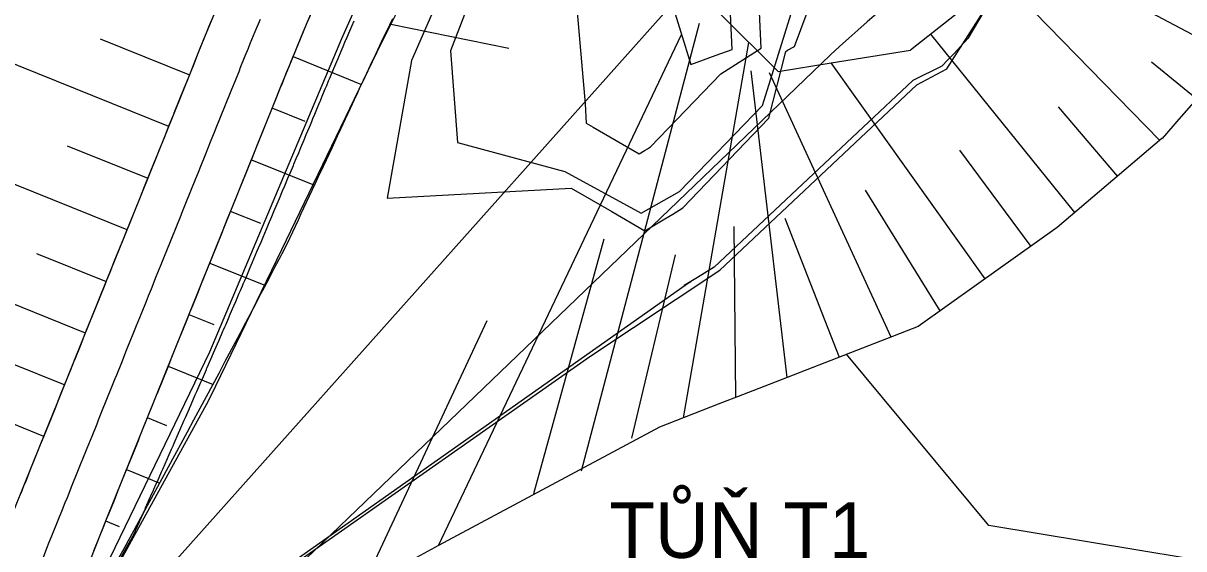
# Model space of a CAD drawing. Extents: x -564037 to -563722, y -1163561 to -1163412.
# Drawn here: x -563977.45 to -563951.42, y -1163497.4 to -1163485.61 of the extents above; entities that cross this region are included whole.
import ezdxf

# ---------------------------------------------------------------- set-up
doc = ezdxf.new("R2010")
doc.units = 0
for name, color, linetype in [('4', 7, 'Continuous'), ('5', 7, 'Continuous'), ('Default', 7, 'Continuous'), ('Line', 7, 'Continuous')]:
    doc.layers.add(name, color=color, linetype=linetype)

msp = doc.modelspace()

# ---------------------------------------------------------------- linework, layer by layer
for points in [[(-563976.663, -1163501.462), (-563964.742, -1163493.091), (-563961.829, -1163491.15), (-563957.41, -1163486.988), (-563956.735, -1163486.627), (-563953.281, -1163481.221), (-563953.993, -1163478.343), (-563957.796, -1163470.824), (-563957.81, -1163470.439), (-563957.835, -1163469.754), (-563958.239, -1163469.063), (-563958.187, -1163468.683), (-563959.529, -1163466.077), (-563960.166, -1163464.984), (-563964.31, -1163473.527), (-563966.903, -1163478.544), (-563968.406, -1163481.669), (-563970.316, -1163485.955), (-563973.278, -1163492.988), (-563976.735, -1163500.155), (-563977.161, -1163500.889), (-563977.363, -1163501.307)], [(-563962.125, -1163475.875), (-563962.765, -1163475.108), (-563963.856, -1163475.351), (-563965.212, -1163477.785), (-563966.919, -1163483.486), (-563967.557, -1163485.407), (-563967.871, -1163486.226), (-563967.716, -1163488.285), (-563965.306, -1163488.933), (-563963.594, -1163489.868), (-563962.736, -1163489.387), (-563960.869, -1163487.453), (-563959.333, -1163482.497), (-563959.613, -1163479.666)], [(-563962.48, -1163486.536), (-563961.911, -1163486.326), (-563961.553, -1163486.194), (-563961.747, -1163482.024), (-563961.878, -1163479.201), (-563962.246, -1163479.103), (-563962.794, -1163479.244), (-563962.818, -1163479.245), (-563963.128, -1163481.546), (-563962.901, -1163485.181)]]:
    msp.add_lwpolyline(points, close=True)
for points in [[(-563975.396, -1163497.906), (-563973.296, -1163494.084), (-563973.133, -1163493.747), (-563971.654, -1163490.682), (-563969.513, -1163486.248), (-563968.702, -1163484.611), (-563968.142, -1163483.478), (-563966.349, -1163479.855), (-563965.958, -1163479.067), (-563964.584, -1163476.289), (-563963.373, -1163473.843), (-563963.192, -1163473.475), (-563963.191, -1163473.474), (-563962.456, -1163471.989), (-563961.948, -1163470.647), (-563961.634, -1163469.818)], [(-563960.523, -1163486.688), (-563961.829, -1163485.385), (-563962.324, -1163483.708), (-563962.461, -1163482.584), (-563962.597, -1163481.459), (-563962.579, -1163480.501), (-563961.736, -1163479.195), (-563961.088, -1163479.165), (-563960.669, -1163479.145), (-563960.089, -1163479.118), (-563959.09, -1163479.072), (-563958.091, -1163479.026), (-563957.266, -1163478.987), (-563957.092, -1163478.979), (-563955.995, -1163480.274), (-563955.699, -1163482.25), (-563955.954, -1163483.392), (-563956.177, -1163485.128), (-563956.177, -1163485.128), (-563956.177, -1163485.128), (-563957.55, -1163486.21)], [(-563965.051, -1163485.101), (-563964.85, -1163487.418), (-563964.83, -1163487.847), (-563964.668, -1163487.941), (-563963.636, -1163488.535), (-563963.502, -1163488.454), (-563963.449, -1163488.423), (-563963.381, -1163488.382), (-563961.809, -1163486.742), (-563960.902, -1163486.164), (-563961.157, -1163480.663)], [(-563968.084, -1163484.934), (-563968.744, -1163486.445), (-563969.289, -1163489.534), (-563965.164, -1163489.309), (-563965.164, -1163489.309), (-563964.25, -1163489.835), (-563963.508, -1163490.263), (-563963.061, -1163489.994), (-563962.883, -1163489.889), (-563962.657, -1163489.751), (-563960.727, -1163487.738), (-563960.348, -1163486.241), (-563960.31, -1163486.212), (-563960.154, -1163486.129), (-563958.95, -1163482.892)], [(-563977.812, -1163496.922), (-563977.438, -1163495.994), (-563977.065, -1163495.066), (-563976.691, -1163494.139), (-563976.318, -1163493.211), (-563975.945, -1163492.283), (-563975.571, -1163491.355), (-563975.198, -1163490.428), (-563974.825, -1163489.5), (-563974.451, -1163488.572), (-563974.078, -1163487.645), (-563973.705, -1163486.717), (-563973.527, -1163486.276), (-563973.328, -1163485.785), (-563972.941, -1163484.852)], [(-563975.956, -1163497.668), (-563975.583, -1163496.741), (-563975.209, -1163495.813), (-563974.836, -1163494.885), (-563974.463, -1163493.958), (-563974.089, -1163493.03), (-563973.716, -1163492.102), (-563973.343, -1163491.175), (-563972.969, -1163490.247), (-563972.596, -1163489.319), (-563972.223, -1163488.391), (-563971.849, -1163487.464), (-563971.672, -1163487.023), (-563971.476, -1163486.542), (-563971.097, -1163485.627), (-563970.817, -1163484.966)], [(-563977.502, -1163496.152), (-563977.438, -1163495.994), (-563977.391, -1163495.877), (-563977.28, -1163495.601), (-563977.169, -1163495.326), (-563977.065, -1163495.066), (-563977.059, -1163495.051), (-563976.948, -1163494.775), (-563976.837, -1163494.5), (-563976.726, -1163494.225), (-563976.691, -1163494.139), (-563976.615, -1163493.949), (-563976.505, -1163493.674), (-563976.394, -1163493.399), (-563976.318, -1163493.211), (-563976.283, -1163493.123), (-563976.172, -1163492.848), (-563976.061, -1163492.573), (-563975.95, -1163492.297), (-563975.945, -1163492.283), (-563975.84, -1163492.022), (-563975.729, -1163491.747), (-563975.618, -1163491.471), (-563975.571, -1163491.355), (-563975.507, -1163491.196), (-563975.396, -1163490.921), (-563975.286, -1163490.645), (-563975.198, -1163490.428), (-563975.175, -1163490.37), (-563975.064, -1163490.095), (-563974.953, -1163489.819), (-563974.842, -1163489.544), (-563974.825, -1163489.5), (-563974.732, -1163489.269), (-563974.621, -1163488.994), (-563974.51, -1163488.718), (-563974.451, -1163488.572), (-563974.399, -1163488.443), (-563974.288, -1163488.168), (-563974.177, -1163487.892), (-563974.078, -1163487.645), (-563974.067, -1163487.617), (-563973.956, -1163487.342), (-563973.845, -1163487.066), (-563973.734, -1163486.791), (-563973.705, -1163486.717), (-563973.623, -1163486.516), (-563973.527, -1163486.276), (-563973.512, -1163486.24), (-563973.4, -1163485.962), (-563973.328, -1163485.785), (-563973.287, -1163485.685), (-563973.173, -1163485.407)], [(-563977.017, -1163497.627), (-563976.907, -1163497.351), (-563976.884, -1163497.295), (-563976.796, -1163497.076), (-563976.685, -1163496.801), (-563976.574, -1163496.525), (-563976.511, -1163496.367), (-563976.463, -1163496.25), (-563976.353, -1163495.975), (-563976.242, -1163495.699), (-563976.137, -1163495.44), (-563976.131, -1163495.424), (-563976.02, -1163495.149), (-563975.909, -1163494.873), (-563975.798, -1163494.598), (-563975.764, -1163494.512), (-563975.688, -1163494.323), (-563975.577, -1163494.047), (-563975.466, -1163493.772), (-563975.39, -1163493.584), (-563975.355, -1163493.497), (-563975.244, -1163493.221), (-563975.134, -1163492.946), (-563975.023, -1163492.671), (-563975.017, -1163492.657), (-563974.912, -1163492.395), (-563974.801, -1163492.12), (-563974.69, -1163491.845), (-563974.644, -1163491.729), (-563974.58, -1163491.569), (-563974.469, -1163491.294), (-563974.358, -1163491.019), (-563974.27, -1163490.801), (-563974.247, -1163490.744), (-563974.136, -1163490.468), (-563974.025, -1163490.193), (-563973.915, -1163489.918), (-563973.897, -1163489.873), (-563973.804, -1163489.642), (-563973.693, -1163489.367), (-563973.582, -1163489.092), (-563973.524, -1163488.946), (-563973.471, -1163488.816), (-563973.361, -1163488.541), (-563973.25, -1163488.266), (-563973.15, -1163488.018), (-563973.139, -1163487.99), (-563973.028, -1163487.715), (-563972.917, -1163487.44), (-563972.807, -1163487.164), (-563972.777, -1163487.09), (-563972.696, -1163486.889), (-563972.599, -1163486.649), (-563972.585, -1163486.614), (-563972.474, -1163486.339), (-563972.402, -1163486.163), (-563972.361, -1163486.064), (-563972.249, -1163485.789), (-563972.135, -1163485.515)], [(-563975.868, -1163497.449), (-563975.757, -1163497.174), (-563975.646, -1163496.899), (-563975.583, -1163496.741), (-563975.536, -1163496.623), (-563975.425, -1163496.348), (-563975.314, -1163496.073), (-563975.209, -1163495.813), (-563975.203, -1163495.797), (-563975.092, -1163495.522), (-563974.982, -1163495.247), (-563974.871, -1163494.971), (-563974.836, -1163494.885), (-563974.76, -1163494.696), (-563974.649, -1163494.421), (-563974.538, -1163494.145), (-563974.463, -1163493.958), (-563974.428, -1163493.87), (-563974.317, -1163493.595), (-563974.206, -1163493.319), (-563974.095, -1163493.044), (-563974.089, -1163493.03), (-563973.984, -1163492.769), (-563973.873, -1163492.493), (-563973.763, -1163492.218), (-563973.716, -1163492.102), (-563973.652, -1163491.943), (-563973.541, -1163491.668), (-563973.43, -1163491.392), (-563973.343, -1163491.175), (-563973.319, -1163491.117), (-563973.209, -1163490.842), (-563973.098, -1163490.566), (-563972.987, -1163490.291), (-563972.969, -1163490.247), (-563972.876, -1163490.016), (-563972.765, -1163489.74), (-563972.655, -1163489.465), (-563972.596, -1163489.319), (-563972.544, -1163489.19), (-563972.433, -1163488.914), (-563972.322, -1163488.639), (-563972.223, -1163488.391), (-563972.211, -1163488.364), (-563972.101, -1163488.088), (-563971.99, -1163487.813), (-563971.879, -1163487.538), (-563971.849, -1163487.464), (-563971.768, -1163487.262), (-563971.672, -1163487.023), (-563971.657, -1163486.987), (-563971.547, -1163486.715), (-563971.476, -1163486.542), (-563971.436, -1163486.443), (-563971.324, -1163486.171), (-563971.212, -1163485.9), (-563971.098, -1163485.629), (-563971.097, -1163485.627), (-563970.984, -1163485.358)], [(-563975.336, -1163497.663), (-563975.193, -1163497.401), (-563975.049, -1163497.139), (-563974.967, -1163496.989), (-563974.906, -1163496.877), (-563974.763, -1163496.614), (-563974.62, -1163496.352), (-563974.485, -1163496.104), (-563974.477, -1163496.09), (-563974.335, -1163495.827), (-563974.192, -1163495.564), (-563974.05, -1163495.302), (-563974.006, -1163495.219), (-563973.909, -1163495.039), (-563973.767, -1163494.776), (-563973.625, -1163494.513), (-563973.529, -1163494.333), (-563973.484, -1163494.25), (-563973.343, -1163493.987), (-563973.202, -1163493.723), (-563973.062, -1163493.46), (-563973.055, -1163493.446), (-563972.922, -1163493.196), (-563972.782, -1163492.933), (-563972.642, -1163492.669), (-563972.583, -1163492.558), (-563972.502, -1163492.405), (-563972.363, -1163492.142), (-563972.224, -1163491.878), (-563972.114, -1163491.669), (-563972.085, -1163491.614), (-563971.946, -1163491.35), (-563971.808, -1163491.085), (-563971.669, -1163490.821), (-563971.647, -1163490.779), (-563971.537, -1163490.555), (-563971.41, -1163490.286), (-563971.283, -1163490.017), (-563971.216, -1163489.874), (-563971.157, -1163489.748), (-563971.03, -1163489.479), (-563970.904, -1163489.21), (-563970.791, -1163488.968), (-563970.778, -1163488.94), (-563970.653, -1163488.671), (-563970.527, -1163488.402), (-563970.402, -1163488.132), (-563970.368, -1163488.06), (-563970.277, -1163487.863), (-563970.168, -1163487.628), (-563970.152, -1163487.594), (-563970.03, -1163487.332), (-563969.952, -1163487.164), (-563969.908, -1163487.069), (-563969.785, -1163486.808), (-563969.662, -1163486.546), (-563969.538, -1163486.285), (-563969.537, -1163486.283), (-563969.414, -1163486.024), (-563969.289, -1163485.763), (-563969.233, -1163485.646), (-563969.164, -1163485.502)], [(-563975.336, -1163497.663), (-563975.193, -1163497.401), (-563975.049, -1163497.139), (-563974.967, -1163496.989), (-563974.906, -1163496.877), (-563974.763, -1163496.614), (-563974.62, -1163496.352), (-563974.485, -1163496.104), (-563974.477, -1163496.09), (-563974.335, -1163495.827), (-563974.192, -1163495.564), (-563974.05, -1163495.302), (-563974.006, -1163495.219), (-563973.909, -1163495.039), (-563973.767, -1163494.776), (-563973.625, -1163494.513), (-563973.529, -1163494.333), (-563973.484, -1163494.25), (-563973.343, -1163493.987), (-563973.202, -1163493.723), (-563973.062, -1163493.46), (-563973.055, -1163493.446), (-563972.922, -1163493.196), (-563972.782, -1163492.933), (-563972.642, -1163492.669), (-563972.583, -1163492.558), (-563972.502, -1163492.405), (-563972.363, -1163492.142), (-563972.224, -1163491.878), (-563972.114, -1163491.669), (-563972.085, -1163491.614), (-563971.946, -1163491.35), (-563971.808, -1163491.085), (-563971.669, -1163490.821), (-563971.647, -1163490.779), (-563971.537, -1163490.555), (-563971.41, -1163490.286), (-563971.283, -1163490.017), (-563971.216, -1163489.874), (-563971.157, -1163489.748), (-563971.03, -1163489.479), (-563970.904, -1163489.21), (-563970.791, -1163488.968), (-563970.778, -1163488.94), (-563970.653, -1163488.671), (-563970.527, -1163488.402), (-563970.402, -1163488.132), (-563970.368, -1163488.06), (-563970.277, -1163487.863), (-563970.168, -1163487.628), (-563970.152, -1163487.594), (-563970.03, -1163487.332), (-563969.952, -1163487.164), (-563969.908, -1163487.069), (-563969.785, -1163486.808), (-563969.662, -1163486.546), (-563969.538, -1163486.285), (-563969.537, -1163486.283), (-563969.414, -1163486.024), (-563969.289, -1163485.763), (-563969.233, -1163485.646), (-563969.164, -1163485.502)], [(-563960.523, -1163486.688), (-563959.331, -1163486.495), (-563957.55, -1163486.21)], [(-563950.476, -1163486.561), (-563951.53, -1163487.762), (-563951.667, -1163487.917), (-563951.91, -1163488.194), (-563951.913, -1163488.197), (-563954.263, -1163490.192), (-563956.079, -1163491.487), (-563957.379, -1163492.414), (-563960.591, -1163493.664), (-563961.319, -1163493.948), (-563961.866, -1163494.161), (-563963.182, -1163494.674), (-563968.138, -1163497.33), (-563968.634, -1163497.596)], [(-563940.257, -1163499.457), (-563955.795, -1163496.878), (-563958.985, -1163493.039)]]:
    msp.add_lwpolyline(points)
at = {"layer": '5'}
msp.add_line((-563974.94, -1163501.303), (-563959.546, -1163486.507), dxfattribs=at)
msp.add_arc((-563942.222, -1163504.531), 25, 113.6313, 133.8653, dxfattribs=at)
at = {"layer": 'Default'}
for points in [[(-563957.93, -1163469.965), (-563958.016, -1163470.367), (-563958.027, -1163470.695), (-563958.032, -1163470.72), (-563958.032, -1163470.72), (-563954.123, -1163478.457), (-563954.123, -1163478.457), (-563954.123, -1163478.457), (-563954.115, -1163478.547), (-563954.115, -1163478.547), (-563953.444, -1163481.184), (-563956.263, -1163485.948), (-563956.577, -1163486.293), (-563956.711, -1163486.426), (-563956.848, -1163486.572), (-563957.497, -1163486.891), (-563961.953, -1163491.085), (-563962.333, -1163491.316), (-563962.631, -1163491.492), (-563962.482, -1163491.404), (-563976.56, -1163501.343)], [(-563977.332, -1163501.295), (-563974.976, -1163497.082), (-563974.974, -1163497.079), (-563974.939, -1163497), (-563974.935, -1163496.992), (-563974.849, -1163496.797), (-563974.841, -1163496.78), (-563974.722, -1163496.513), (-563974.711, -1163496.488), (-563974.596, -1163496.229), (-563974.589, -1163496.212), (-563974.532, -1163496.085), (-563974.525, -1163496.068), (-563974.47, -1163495.944), (-563974.453, -1163495.906), (-563974.344, -1163495.659), (-563974.324, -1163495.615), (-563974.218, -1163495.374), (-563974.203, -1163495.339), (-563974.128, -1163495.17), (-563974.122, -1163495.155), (-563974.093, -1163495.09), (-563974.069, -1163495.034), (-563973.968, -1163494.805), (-563973.941, -1163494.744), (-563973.843, -1163494.52), (-563973.816, -1163494.459), (-563973.727, -1163494.254), (-563973.725, -1163494.249), (-563973.718, -1163494.234), (-563973.688, -1163494.165), (-563973.594, -1163493.949), (-563973.562, -1163493.876), (-563973.47, -1163493.664), (-563973.436, -1163493.586), (-563973.346, -1163493.378), (-563973.341, -1163493.366), (-563973.328, -1163493.337), (-563973.297, -1163493.267), (-563973.222, -1163493.093), (-563973.185, -1163493.008), (-563973.099, -1163492.807), (-563973.061, -1163492.719), (-563972.975, -1163492.522), (-563972.961, -1163492.488), (-563972.931, -1163492.418), (-563972.905, -1163492.359), (-563972.852, -1163492.236), (-563972.812, -1163492.141), (-563972.729, -1163491.95), (-563972.688, -1163491.852), (-563972.607, -1163491.664), (-563972.582, -1163491.606), (-563972.536, -1163491.499), (-563972.518, -1163491.456), (-563972.485, -1163491.378), (-563972.441, -1163491.275), (-563972.363, -1163491.092), (-563972.318, -1163490.986), (-563972.241, -1163490.805), (-563972.204, -1163490.719), (-563972.145, -1163490.579), (-563972.135, -1163490.556), (-563972.119, -1163490.519), (-563972.072, -1163490.408), (-563971.998, -1163490.232), (-563971.95, -1163490.12), (-563971.877, -1163489.946), (-563971.829, -1163489.833), (-563971.756, -1163489.659), (-563971.756, -1163489.659), (-563971.755, -1163489.658), (-563971.707, -1163489.544), (-563971.635, -1163489.372), (-563971.587, -1163489.257), (-563971.515, -1163489.086), (-563971.466, -1163488.969), (-563971.395, -1163488.799), (-563971.384, -1163488.773), (-563971.368, -1163488.735), (-563971.33, -1163488.644), (-563971.275, -1163488.512), (-563971.225, -1163488.393), (-563971.155, -1163488.224), (-563971.105, -1163488.105), (-563971.036, -1163487.937), (-563971.014, -1163487.885), (-563970.984, -1163487.812), (-563970.955, -1163487.744), (-563970.916, -1163487.65), (-563970.868, -1163487.533), (-563970.802, -1163487.373), (-563970.8, -1163487.368), (-563970.797, -1163487.363), (-563970.747, -1163487.242), (-563970.68, -1163487.081), (-563970.647, -1163487.002), (-563970.604, -1163486.898), (-563970.586, -1163486.855), (-563970.563, -1163486.799), (-563970.511, -1163486.677), (-563970.445, -1163486.518), (-563970.392, -1163486.395), (-563970.326, -1163486.237), (-563970.28, -1163486.13), (-563970.222, -1163485.995), (-563970.215, -1163485.978), (-563970.206, -1163485.957), (-563970.153, -1163485.832), (-563970.086, -1163485.676), (-563970.032, -1163485.551)]]:
    msp.add_lwpolyline(points, dxfattribs=at)
at = {"layer": 'Line'}
for p, q in [((-563950.389, -1163486.314), (-563955.948, -1163483.346)), ((-563951.96, -1163488.236), (-563956.04, -1163484.057)), ((-563962.901, -1163485.181), (-563977.279, -1163501.298)), ((-563966.564, -1163486.174), (-563969.208, -1163485.632)), ((-563964.928, -1163495.656), (-563962.285, -1163485.606)), ((-563964.928, -1163495.656), (-563962.285, -1163485.606)), ((-563975.726, -1163485.954), (-563973.723, -1163486.764)), ((-563968.138, -1163497.33), (-563962.69, -1163485.858)), ((-563968.138, -1163497.33), (-563962.69, -1163485.858)), ((-563962.645, -1163494.465), (-563961.176, -1163486.037)), ((-563953.865, -1163489.855), (-563957.097, -1163485.853)), ((-563971.398, -1163486.352), (-563969.867, -1163486.983)), ((-563974.19, -1163487.923), (-563977.994, -1163486.392)), ((-563955.874, -1163491.341), (-563959.329, -1163486.494)), ((-563952.148, -1163486.471), (-563951.128, -1163487.304)), ((-563960.316, -1163493.557), (-563961.127, -1163486.674)), ((-563957.986, -1163492.65), (-563960.711, -1163486.719)), ((-563971.129, -1163487.809), (-563971.868, -1163487.51)), ((-563954.241, -1163487.481), (-563952.912, -1163489.046)), ((-563976.466, -1163488.355), (-563974.657, -1163489.083)), ((-563972.335, -1163488.67), (-563970.918, -1163489.24)), ((-563956.456, -1163488.453), (-563954.856, -1163490.615)), ((-563975.123, -1163490.242), (-563978.542, -1163488.867)), ((-563958.571, -1163489.355), (-563956.892, -1163492.066)), ((-563972.126, -1163490.101), (-563972.801, -1163489.829)), ((-563960.367, -1163489.982), (-563959.151, -1163493.104)), ((-563961.513, -1163490.172), (-563961.48, -1163494.011)), ((-563964.431, -1163490.456), (-563966.005, -1163496.172)), ((-563964.431, -1163490.456), (-563966.005, -1163496.172)), ((-563977.155, -1163490.772), (-563975.59, -1163491.402)), ((-563973.268, -1163490.989), (-563972.021, -1163491.491)), ((-563962.83, -1163490.808), (-563963.81, -1163494.918)), ((-563962.83, -1163490.808), (-563963.81, -1163494.918)), ((-563976.057, -1163492.562), (-563978.885, -1163491.423)), ((-563973.171, -1163492.376), (-563973.735, -1163492.149)), ((-563967.053, -1163492.285), (-563969.789, -1163498.142)), ((-563967.053, -1163492.285), (-563969.789, -1163498.142)), ((-563977.783, -1163493.214), (-563976.523, -1163493.721)), ((-563974.201, -1163493.308), (-563973.196, -1163493.713)), ((-563976.99, -1163494.881), (-563979.193, -1163493.994)), ((-563974.23, -1163494.644), (-563974.668, -1163494.468)), ((-563975.135, -1163495.627), (-563974.389, -1163495.928)), ((-563975.296, -1163496.91), (-563975.602, -1163496.787))]:
    msp.add_line(p, q, dxfattribs=at)

# ---------------------------------------------------------------- texts
at = {"layer": '4'}
msp.add_text('TŮŇ T1', height=1.25, rotation=360, dxfattribs=at).set_placement((-563964.304, -1163497.609))

doc.saveas('drawing.dxf')
